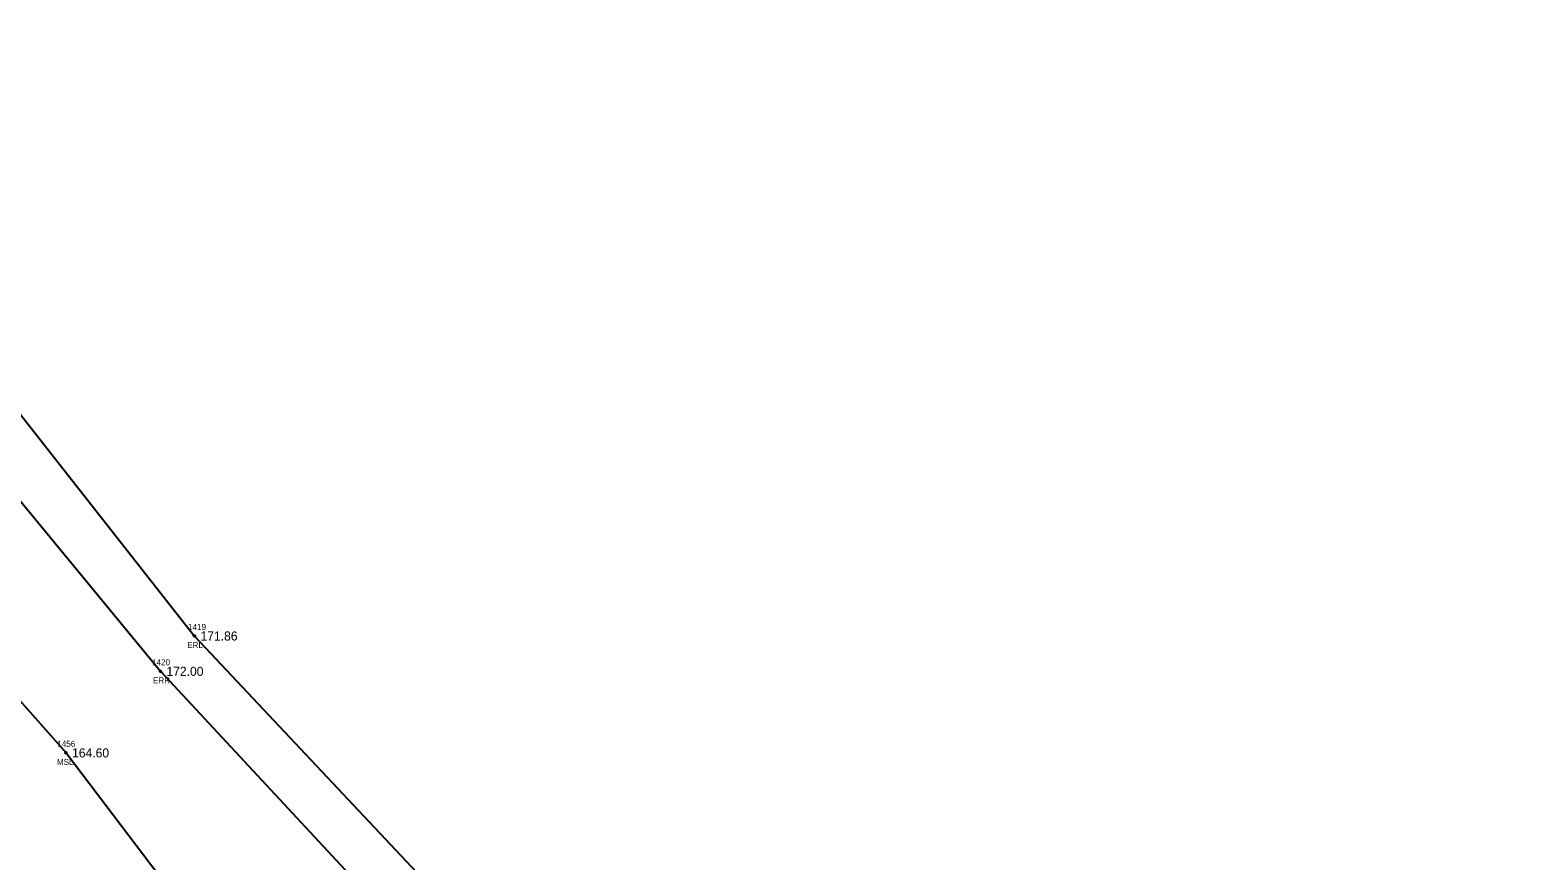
# Model space of a CAD drawing. Extents: x 1969685 to 1970577, y 796315 to 797503.
# Drawn here: x 1970128.7 to 1970378.4, y 796967.3 to 797104.8 of the extents above; entities that cross this region are included whole.
import ezdxf

# ---------------------------------------------------------------- set-up
doc = ezdxf.new("R2010")
doc.units = 0
for name, color, linetype in [('RD_EX_Misc', 7, 'Continuous'), ('RD_EX_Misc_txCode', 7, 'Continuous'), ('RD_EX_Road', 7, 'Continuous'), ('RD_EX_Road_txCode', 7, 'Continuous'), ('RD_EX_TX_Misc_ELEV', 7, 'Continuous'), ('RD_EX_TX_Road_ELEV', 7, 'Continuous'), ('RD_SMD_Locator', 7, 'Continuous')]:
    doc.layers.add(name, color=color, linetype=linetype)

msp = doc.modelspace()

# ---------------------------------------------------------------- linework, layer by layer
at = {"layer": 'RD_EX_Misc'}
msp.add_lwpolyline([(1970119.68, 797002.07), (1970134.67, 796985.14), (1970155.26, 796957.98), (1970184.14, 796927.08), (1970200, 796908.86), (1970214.83, 796881.9), (1970223.07, 796860.85), (1970237.12, 796840.22), (1970247.97, 796828.57), (1970264.98, 796797.04), (1970268.55, 796760.45), (1970285.4, 796719.08), (1970289.98, 796692.37), (1970293.21, 796649.04), (1970312.17, 796610.64), (1970319.99, 796568.49), (1970324.17, 796540.99), (1970330.09, 796500.77), (1970344.67, 796440.73), (1970352.86, 796398.26), (1970358.68, 796366.34), (1970371.75, 796316.87)], dxfattribs=at)
at = {"layer": 'RD_EX_Road'}
for points in [[(1969700.74, 797501.33), (1969779.98, 797423.39), (1969814.72, 797391.2), (1969880.84, 797321.11), (1969950.92, 797234.98), (1970023.24, 797160.71), (1970094.63, 797082.52), (1970155.94, 797004.5), (1970226.04, 796929.95), (1970305.25, 796840.26), (1970331.41, 796808.37), (1970366.95, 796762.12), (1970420.55, 796674.34), (1970475.41, 796571.94), (1970519.62, 796482.24), (1970570.43, 796387.6)], [(1969686.81, 797489.23), (1969769.62, 797412.05), (1969806.95, 797381.52), (1969873.82, 797315.12), (1969942.63, 797227.86), (1970016.3, 797154.94), (1970086.97, 797075.58), (1970150.3, 796998.65), (1970220.21, 796923.5), (1970297.55, 796833.97), (1970324.51, 796802.07), (1970359.87, 796756.6), (1970413.8, 796671.17), (1970467.81, 796568.38), (1970512.42, 796477.88), (1970563.2, 796383.6)]]:
    msp.add_lwpolyline(points, dxfattribs=at)
at = {"layer": 'RD_SMD_Locator'}
for centre in [(1970155.94, 797004.5), (1970150.3, 796998.65), (1970134.67, 796985.14)]:
    msp.add_circle(centre, 0.15, dxfattribs=at)

# ---------------------------------------------------------------- texts
at = {"layer": 'RD_EX_Misc_txCode'}
for s, p in [('1456', (1970133.22, 796986.14)), ('MSL', (1970133.17, 796983.14))]:
    msp.add_text(s, height=1, dxfattribs=at).set_placement(p)
at = {"layer": 'RD_EX_Road_txCode'}
for s, p in [('1419', (1970154.88, 797005.5)), ('ERL', (1970154.74, 797002.5)), ('1420', (1970148.92, 796999.65)), ('ERR', (1970149.07, 796996.65))]:
    msp.add_text(s, height=1, dxfattribs=at).set_placement(p)
at = {"layer": 'RD_EX_TX_Misc_ELEV'}
msp.add_text('164.60', height=1.5, dxfattribs=at).set_placement((1970135.67, 796984.39))
at = {"layer": 'RD_EX_TX_Road_ELEV'}
for s, p in [('171.86', (1970156.94, 797003.75)), ('172.00', (1970151.3, 796997.9))]:
    msp.add_text(s, height=1.5, dxfattribs=at).set_placement(p)

doc.saveas('drawing.dxf')
